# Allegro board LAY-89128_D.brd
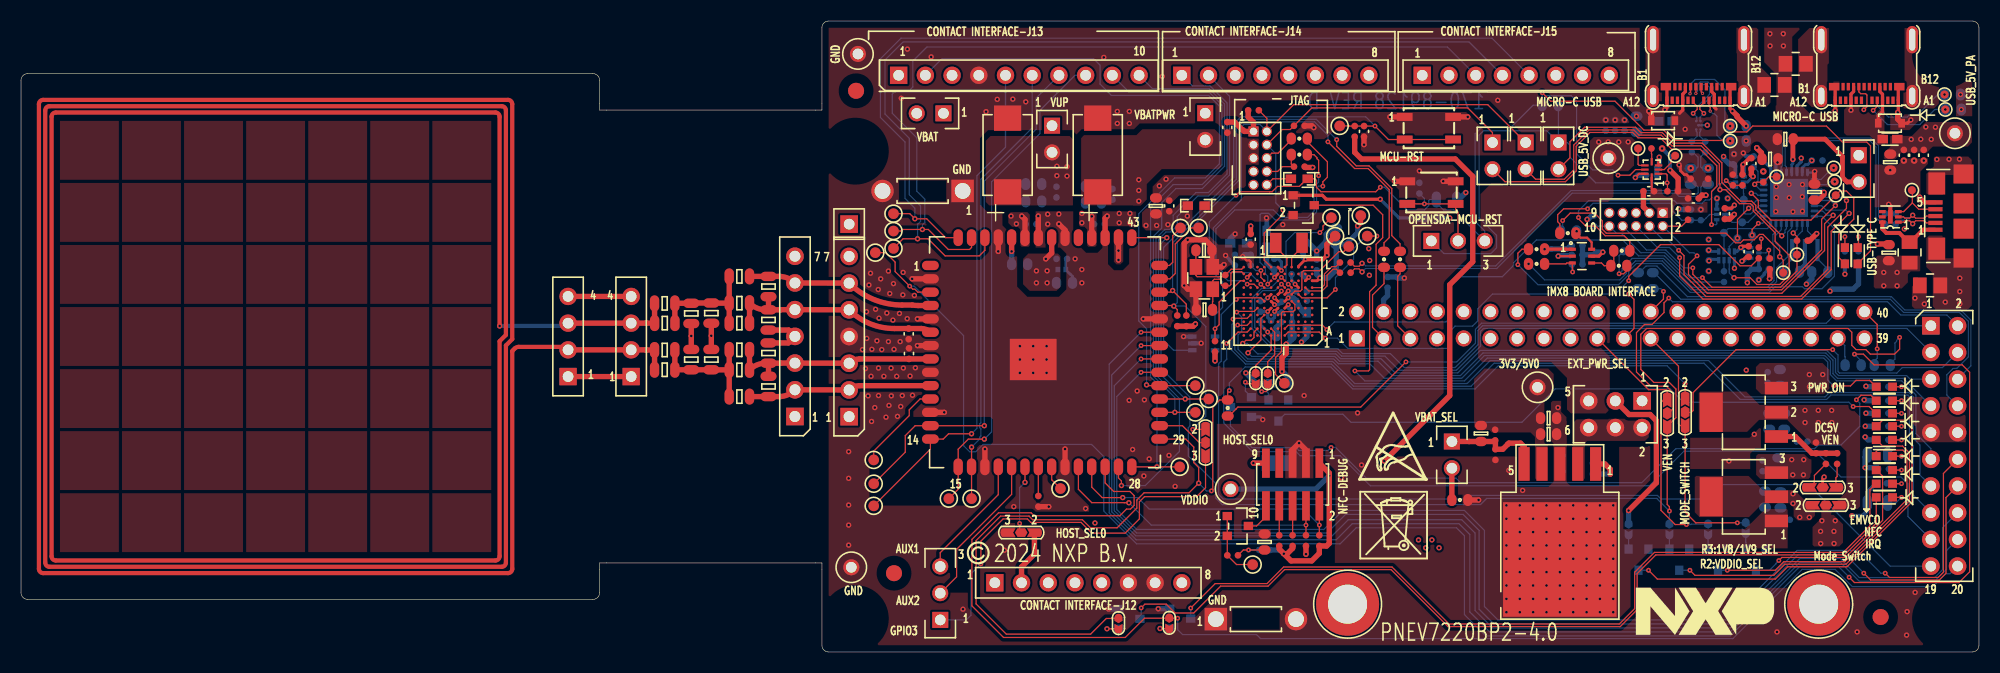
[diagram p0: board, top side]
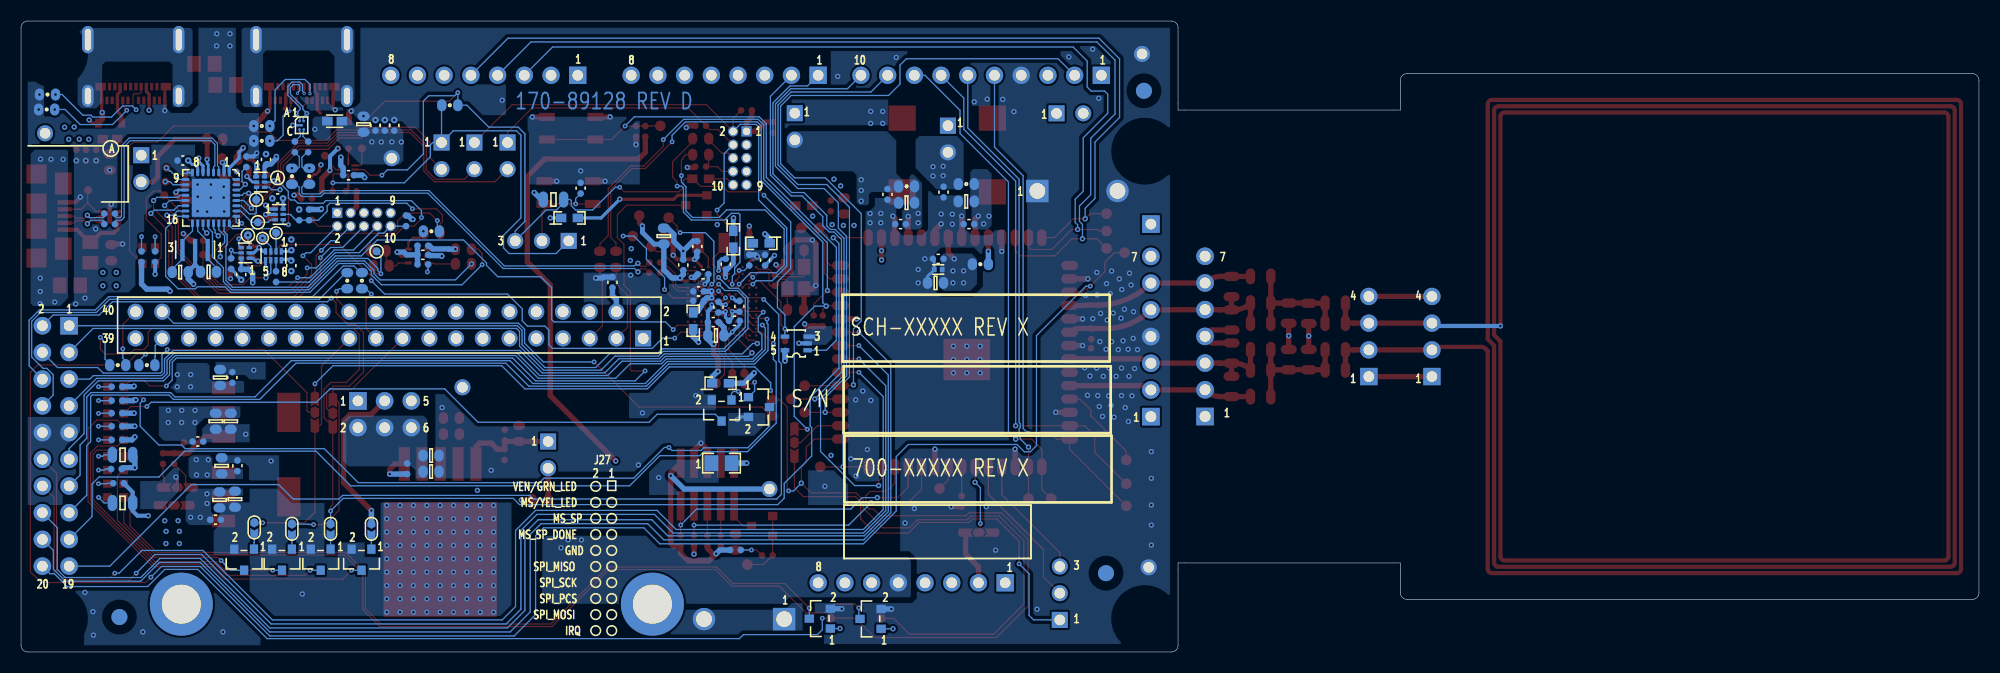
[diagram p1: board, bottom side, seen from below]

Outline 186.16 x 60 mm; copper layers: TOP, L2_GND_1, L3_INT_1, BOTTOM. Coordinates in mm from the lower left corner of the outline.
Outline path: 0,54.37 0,5.63 arc(0.19,5.19) 0.63,5 54.38,5 arc(54.83,5.19) 55.01,5.63 55.01,8.47 76.15,8.47 76.15,0.63 arc(76.33,0.19) 76.78,0 185.52,0 arc(185.97,0.19) 186.16,0.63 186.16,59.37 arc(185.97,59.81) 185.52,60 76.78,60 arc(76.33,59.81) 76.15,59.37 76.15,51.53 55.01,51.53 55.01,54.37 arc(54.83,54.81) 54.38,55 0.63,55 arc(0.19,54.81) 0,54.37

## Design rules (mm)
constraint set DEFAULT: min track width 0.114
net group SDA_USB_CONN_DN: nets SDA_USB_CONN_DN SDA_USB_DN
net group SDA_USB_CONN_DP: nets SDA_USB_CONN_DP SDA_USB_DP
net group USB_CC: nets USB_CC1_PA USB_CC2_PA
net group USB_CC_DC: nets USB_CC1_DC USB_CC2_DC
net group USB_DP1: nets USB_DN USB_DP
net group POWER: nets 3V3_K82_VOUT MCU_VBAT MCU_VDDA P5V0_SDA_USB_CONN_VBUS SH_3V3_VDDIO_E VDDPA VREF_OUT
net group USB0_DM: nets N28673663 N28673665 USB0_DM USB0_RDN
net group USB0_DP: nets N28673617 N28673619 USB0_DP USB0_RDP

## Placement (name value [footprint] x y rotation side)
C1  0.1uF  [CC0402_25]  165.58 17.7 90 bottom
C2  0.1uF  [CC0402_25]  166.07 26.1 90 bottom
C3  0.1uF  [CC0402_25]  102.53 40.69 0 bottom
C4  0.1uF  [CC0402_25]  96.03 40.69 0 bottom
C5  100UF  [CC7343]  93.8 47.26 90 top
C7  100UF  [CC7343]  102.37 47.26 90 top
C9  10uF  [CC0603_OV]  165.81 14.53 270 bottom
C10  0.1uF  [CC0402_25]  98.95 37.38 0 bottom
C11  0.1uF  [CC0402_25]  98.45 43.73 270 bottom
C14  10uF  [CC0603_OV]  147.17 18.68 180 bottom
C15  10uF  [CC0603_OV]  145.24 20.71 0 top
C16  10uF  [CC0603_OV]  107.91 42.42 90 top
C17  10uF  [CC0603_OV]  167.08 17.7 90 bottom
C19  0.1uF  [CC0402_25]  109.17 42.42 90 top
C20  680pF  [CC0603_OV]  138.81 20.78 270 top
C23  10uF  [CC0603_OV]  101.96 42.72 0 bottom
C24  4.7uF  [CC0603_OV]  177.72 46.58 270 top
C25  1.0UF  [0402_CC]  98.95 36.37 0 bottom
C26  0.1uF  [CC0402_25]  103.78 43.52 270 bottom
C28  10uF  [CC0603_OV]  167.64 21.94 270 bottom
C29  0.1uF  [CC0402_25]  167.66 12.57 180 bottom
C30  10uF  [CC0603_OV]  166.21 21.94 270 bottom
C31  10uF  [CC0603_OV]  96.29 42.85 0 bottom
C32  10uF  [CC0603_OV]  145.24 22.24 0 top
C33  10uF  [CC0603_OV]  167.23 26.1 90 bottom
C34  10uF  [CC0603_OV]  167.28 14.47 270 bottom
C35  10uF  [CC0603_OV]  99.21 35.1 0 bottom
C37  0.1uF  [CC0402_25]  169.34 20.02 180 bottom
C38  10uF  [CC0603_OV]  147.17 17.16 180 bottom
C41  0.1uF  [CC0402_25]  114.69 49.88 270 top
C44  1uF  [CC0603_OV]  125.04 39.55 90 bottom
C45  0.1uF  [CC0402_25]  123.19 36.8 90 bottom
C47  0.1uF  [CC0402_25]  121.31 35.92 180 bottom
C48  0.1uF  [CC0402_25]  121.87 38.56 90 bottom
C49  0.1uF  [CC0402_25]  120.34 31.37 180 bottom
C50  0.1uF  [CC0402_25]  121.74 33.4 0 bottom
C51  0.1uF  [CC0402_25]  121.74 34.29 0 bottom
C52  0.1uF  [CC0402_25]  119.15 36.88 90 bottom
C53  0.1uF  [CC0402_25]  115.42 37.26 270 bottom
C54  0.1uF  [CC0402_25]  119.85 32.79 90 bottom
C55  0.1uF  [CC0402_25]  117.86 32.87 90 bottom
C56  0.01uF  [CC0402_25]  118.34 31.49 180 bottom
C63  0.1uF  [CC0402_25]  179.01 47.24 270 top
C64  0.01uF  [CC0402_25]  179.99 47.24 270 top
C65  1000pF  [CC0402_25]  180.91 47.24 270 top
C66  4.7uF  [CC0603_OV]  153.59 50.19 90 bottom
C67  0.1uF  [CC0402_25]  152.46 50.08 90 bottom
C68  0.01uF  [CC0402_25]  151.57 50.08 90 bottom
C69  1000pF  [CC0402_25]  150.67 50.08 90 bottom
C78  10uF  [CC0603_OV]  120.09 30.1 180 bottom
C79  0.1uF  [CC0402_25]  154.76 43.81 180 top
C80  0.1uF  [CC0402_25]  147.95 37.77 180 bottom
C81  0.1uF  [CC0402_25]  155.02 45.34 0 bottom
C82  10uF  [CC0603_OV]  170.52 43.74 90 top
C83  1uF  [CC0603_OV]  166.29 46.87 0 top
C84  0.1uF  [CC0402_25]  170.77 46.74 0 bottom
C85  1000pF  [CC0402_25]  132.95 44.11 90 bottom
C86  10uF  [CC0603_OV]  177.58 37.97 90 top
C87  22 PF  [CC0603_OV]  168.33 36.15 0 bottom
C88  22 PF  [CC0603_OV]  171.02 36.12 180 bottom
C89  2.2uF  [CC0603_OV]  167.74 48.77 180 top
C91  10uF  [CC0603_OV]  118.23 10.46 90 top
C92  68pF  [CC0805_OV]  71.07 28.43 90 top
C93  68pF  [CC0805_OV]  71.07 31.57 90 top
C94  0.1uF  [CC0402_25]  164.51 46.46 270 top
C95  68pF  [CC0805_OV]  65.63 32.22 90 top
C96  68pF  [CC0805_OV]  63.73 27.8 90 top
C97  18pF  [CC0805_OV]  68.3 33.17 180 top
C98  100pF  [CC0805_OV]  63.73 32.2 90 top
C100  100pF  [CC0805_OV]  65.63 27.8 90 top
C101  47pF  [CC0805_OV]  68.3 28.73 180 top
C102  180pF  [CC0402_25]  84.4 30.25 270 top
C103  18pF  [CC0805_OV]  68.3 26.82 180 top
C104  180pF  [CC0402_25]  84.42 28.37 90 top
C105  47pF  [CC0805_OV]  68.3 31.27 180 top
C134  0.1uF  [CC0402_25]  129.92 35.15 90 bottom
C151  0.1uF  [CC0402_25]  116.92 39.25 90 top
C152  22 PF  [CC0603_OV]  112.47 38.2 180 top
C153  22 PF  [CC0603_OV]  112.52 32.54 0 top
C154  1000pF  [CC0402_25]  127.69 49.51 270 top
C155  0.1uF  [CC0402_25]  164.26 38.07 90 top
C156  0.1uF  [CC0402_25]  165.22 35.89 270 bottom
C157  0.1uF  [CC0402_25]  160.46 38.71 90 bottom
C158  0.1uF  [CC0402_25]  160.46 36.73 270 bottom
C159  0.1uF  [CC0402_25]  162.86 46.84 90 bottom
C160  0.1uF  [CC0402_25]  161.99 41.68 270 top
C161  0.1uF  [CC0402_25]  161.75 43.13 0 bottom
C162  0.1uF  [CC0402_25]  159 43.13 0 top
D1  RED  [LED_0603]  177.16 25.22 180 top
D2  RED  [LED_0603]  177.16 22.69 180 top
D3  LED GREEN  [LED_0603]  177.16 23.9 180 top
D4  PESD5V0U1UA,115  [SOD-323-A]  177.69 50.28 0 top
D5  PESD5V0U1UA,115  [SOD-323-A]  156.12 50.53 180 top
D8  RED  [LED_0603]  174.62 37.68 270 top
D9  LED GREEN  [LED_0603]  173.41 37.68 270 top
D11  LED GREEN  [LED_0603]  177.16 14.71 180 top
D12  BAS70-05  [SOT23_A]  115.69 11.98 270 top
D15  ORANGE  [LED_0603]  177.16 16 180 top
D16  LED_YELLOW  [LED_0603]  177.16 17.3 180 top
D17  GREEN  [LED_0603]  177.16 18.62 180 top
D18  BLUE  [LED_0603]  177.16 20.17 180 top
D19  ORANGE  [LED_0603]  177.16 21.46 180 top
J1  HDR 1X2 TH  [HDR_1X2]  98.03 50.05 0 top
J2  HDR 1X2 TH  [HDR_1X2]  112.59 51.24 0 top
J3  HDR 1X2 TH  [HDR_1X2]  136.04 20.02 0 top
J4  HDR 1X2 TH  [HDR_1X2]  87.7 51.22 270 top
J5  HDR_2X3  [HDR203]  154.13 23.88 270 top
J6  105450-0101  [CON24_USB_TYPEC_RA_SMT]  175.49 56.23 180 top
J7  105450-0101  [CON24_USB_TYPEC_RA_SMT]  159.49 56.23 180 top
J8  LB 03 G  [JUMP2_7P62_TH]  113.6 3.12 0 top
J9  LB 03 G  [JUMP2_7P62_TH]  89.53 43.84 180 top
J10  HDR TH 1X3  [HDR103]  87.4 3.05 180 top
J12  SKT_1X8  [CON_SKT1X8_TH]  92.59 6.58 90 top
J13  SKT_1X10  [CON_SKT1X10_TH_104L]  83.44 54.84 90 top
J14  SKT_1X8  [CON_SKT1X8_TH]  110.37 54.84 90 top
J15  SKT_1X8  [CON_SKT1X8_TH]  133.23 54.84 90 top
J27  TSW-110-07-F-D  [HDR210]  181.58 31.02 0 top
J28  FTSH-105-01-L-DV-K  [HDR205_10M_50_SM_K]  120.9 15.93 180 top
J29  CON_1X4  [CON_SKT1X4_TH]  52.01 26.19 180 top
J30  CON_1X4  [CON_SKT1X4_TH]  58.01 26.19 180 top
J31  SKT_1x7  [CON_1X7_SKT_2P54_TH]  78.73 22.38 90 top
J32  SKT_1x7  [CON_1X7_SKT_2P54_TH]  73.58 22.39 90 top
J33  -  [HDR_1X1]  78.73 40.69 0 top
J35  HDR 2X5  [HDR_5X2_FTSH_TH_NSP]  117.18 49.5 0 top
J43  CON_2X20  [CON_SKT2X20_TH]  127.01 29.82 270 bottom
J56  HDR TH 1X3  [HDR103]  134.09 39.09 90 top
J57  ZX62-AB-5P  [MICRO_USB_CONN_9PIN]  184.69 41.45 90 top
J58  HDR 1X2 TH  [SH_HDR102_BOTTOM]  146.18 48.45 0 top
J59  HDR 1X2 TH  [HDR_1X2]  143.05 48.45 0 top
J60  HDR 1X2 TH  [HDR_1X2]  139.9 48.45 0 top
J61  HDR 1X2 TH  [SH_HDR102_BOTTOM]  174.73 47.24 0 top
J62  HDR 2X5  [HDR_5X2_FTSH_TH_NSP]  156.09 41.76 270 top
L4  330 OHM  [IND_0805]  179.56 38 270 top
L5  330 OHM  [IND_0805]  181.51 34.86 180 top
L6  120 OHM@100MHZ  [IND_0603]  177.7 48.77 180 top
L7  330 OHM  [IND_0805]  168.73 55.93 180 top
L8  120 OHM@100MHZ  [IND_0603]  156.34 50.48 0 bottom
L9  330 OHM  [IND_0805]  166.71 53.92 0 top
NOREF  -  []  159.89 49.48 90 top
NOREF#2  -  []  92.76 21.38 90 top
NOREF#3  -  []  173.2 44.08 90 top
NOREF#4  -  []  158.99 52.46 0 top
NOREF#5  -  []  93.84 11.35 0 top
NOREF#6  -  []  112.62 18.66 90 top
NOREF#7  -  []  172.49 52.46 0 top
NOREF#8  -  []  155.17 52.87 90 top
NOREF#9  -  []  76.15 45.75 0 top
NOREF#10  -  [unnamed#2]  176.8 3.32 0 top
NOREF#11  -  []  152.84 11.18 90 top
NOREF#12  -  []  171.17 52.87 90 top
NOREF#13  -  []  92.47 42.84 90 top
NOREF#14  -  []  170.04 15.65 0 top
NOREF#15  -  []  155.17 52.87 0 top
NOREF#16  -  [unnamed#2]  79.32 3.17 0 top
NOREF#17  -  []  147.74 36.54 0 top
NOREF#18  -  []  73.58 22.39 90 top
NOREF#19  -  []  75.85 43.84 0 top
NOREF#20  -  []  76.15 59.37 0 top
NOREF#21  -  []  107.85 8.94 0 top
NOREF#22  -  [unnamed#2]  83 7.49 0 top
NOREF#23  -  []  155.17 52.87 90 top
NOREF#24  -  []  104.34 2.21 90 top
NOREF#25  -  []  -284.54 213.41 0 top
NOREF#26  -  []  79.37 23.9 0 top
NOREF#27  -  []  89.1 17.6 0 top
NOREF#28  -  []  156.49 52.46 0 top
NOREF#29  -  []  172.39 53.76 0 top
NOREF#30  -  []  149.09 36.54 90 top
NOREF#31  -  []  159.28 49.69 0 top
NOREF#32  -  []  113.6 3.12 0 top
NOREF#33  -  []  112.62 19.91 90 top
NOREF#34  -  []  55.01 45.21 0 top
NOREF#35  -  []  158.22 21.54 90 top
NOREF#36  -  []  170.35 13.96 0 top
NOREF#37  -  []  171.17 52.87 90 top
NOREF#38  -  []  95.1 11.35 0 top
NOREF#39  -  []  119.66 2.12 90 top
NOREF#40  -  [unnamed#2]  79.32 47.63 0 top
NOREF#41  -  []  129.06 5.39 0 top
NOREF#42  -  []  79.32 47.63 0 top
NOREF#43  -  []  155.17 52.87 90 top
NOREF#44  -  [unnamed#2]  182.97 3.17 0 top
NOREF#45  -  []  127.33 8.89 0 top
NOREF#46  -  []  147.49 36.99 0 top
NOREF#47  -  []  170.35 13.96 0 top
NOREF#48  -  []  156.72 11.18 90 top
NOREF#49  -  []  185.99 0.21 0 top
NOREF#50  -  []  171.17 52.87 90 top
NOREF#51  -  []  149.33 36.99 90 top
NOREF#52  -  []  153.54 1.63 0 top
NOREF#53  -  []  91.01 9.4 0 top
NOREF#54  -  []  180.06 44.08 0 top
NOREF#55  -  []  81.91 43.84 0 top
NOREF#56  -  []  97.91 21.36 90 top
NOREF#57  -  []  156.51 22.7 90 top
NOREF#58  -  [unnamed#3]  170.92 4.55 0 top
NOREF#59  -  []  159.68 49.69 90 top
NOREF#60  -  []  156.39 53.76 0 top
NOREF#61  -  [unnamed#2]  182.97 56.83 0 top
NOREF#62  -  []  164.06 44.08 0 top
NOREF#63  -  []  109.17 2.23 90 top
NOREF#64  -  []  115.16 2.12 0 top
NOREF#65  -  []  -309.18 -308.18 0 top
NOREF#66  -  []  74.22 23.92 0 top
NOREF#67  -  []  189.2 44.08 90 top
NOREF#68  -  []  159.07 49.48 0 top
NOREF#69  -  []  77.91 1.9 0 top
NOREF#70  -  []  158.22 22.79 90 top
NOREF#71  -  []  182.45 26.16 0 top
NOREF#72  -  []  171.17 52.87 0 top
NOREF#73  -  []  160.4 11.18 90 top
NOREF#74  -  []  175.24 53.76 0 top
NOREF#75  -  [unnamed#3]  126.13 4.55 0 top
NOREF#76  -  []  108.25 20.25 90 top
NOREF#77  -  []  156.51 21.45 90 top
NOREF#78  -  []  75.63 -84.03 0 top
NOREF#79  -  []  86.56 17.71 0 top
NOREF#80  -  []  78.73 22.38 90 top
NOREF#81  -  []  108.15 17.71 90 top
NOREF#82  -  [unnamed#2]  79.39 53.37 0 top
NOREF#83  -  []  159.24 53.76 0 top
NOREF#84  -  []  108.25 20.25 90 top
NOREF#85  -  []  170.04 15.65 0 top
NOREF#86  -  []  174.99 52.46 0 top
NOREF#87  -  []  55.01 12.35 0 top
NOREF#88  -  []  163.98 11.3 90 top
NOREF#89  -  []  107.95 20.81 180 bottom
NOREF#90  -  []  90.07 14.02 0 bottom
NOREF#91  -  []  107.87 14.23 180 bottom
NOREF#92  -  [unnamed#2]  176.8 3.32 180 bottom
NOREF#93  -  [unnamed#2]  79.39 53.37 180 bottom
NOREF#94  -  [unnamed#2]  83 7.49 180 bottom
NOREF#95  -  []  108.05 27.62 180 bottom
P1  PN76xx MODULE BASE  [MODULE56_1P52_23X23MM]  97.36 28.5 0 top
Q1  NX3008NBK  [SOT23_A]  121.95 42.49 270 top
Q2  NX3008NBK  [SOT23_A]  157.66 8.78 0 bottom
Q3  NX3008NBK  [SOT23_A]  153.78 8.78 0 bottom
Q4  NX3008NBK  [SOT23_A]  164.95 8.78 0 bottom
Q5  NX3008NBK  [SOT23_A]  161.34 8.78 0 bottom
Q6  NX3008NBK  [SOT23_A]  105.38 3.15 90 bottom
Q7  NX3008NBK  [SOT23_A]  110.21 3.17 90 bottom
Q8  NX3008NBK  [SOT23_A]  119.55 22.96 0 bottom
Q9  NX3008NBK  [SOT23_A]  115.99 23.29 270 bottom
R1  180  [RC0402_25]  170.66 19.41 270 top
R2  3 PIN 0603 SHORT 1-2  [3PIN_0603_SOLDER_BLOB_JUMPER_SHORT]  171.6 13.96 180 top
R3  3 PIN 0603 SHORT 1-2  [3PIN_0603_SOLDER_BLOB_JUMPER_SHORT]  171.3 15.65 180 top
R4  80.6  [RC0402_25]  171.6 18.39 270 top
R5  2.74K  [RC0402_25]  140.18 18.77 270 top
R6  3.9K  [RC0603_OV]  136.8 14.45 0 top
R7  3 PIN 0603 SHORT 1-2  [3PIN_0603_SOLDER_BLOB_JUMPER_SHORT]  95.1 11.35 0 top
R8  3 PIN 0603 SHORT 1-2  [3PIN_0603_SOLDER_BLOB_JUMPER_SHORT]  112.62 19.91 90 top
R9  33  [RC0402_25]  125.91 37.04 180 top
R10  5.1K  [RC0603_OV]  163.26 50.02 0 bottom
R11  5.1K  [RC0603_OV]  163.26 48.61 0 bottom
R12  27  [RC0402_25]  160.13 48.03 270 bottom
R13  10K  [RC0402_25]  160.4 45.5 270 top
R14  95.3  [RC0402_25]  172.67 18.39 270 top
R15  3 PIN 0603 JUMPER  [3PIN_0603_SOLDER_BLOB_JUMPER]  156.51 22.7 90 top
R16  3 PIN 0603 SHORT 1-2  [3PIN_0603_SOLDER_BLOB_JUMPER_SHORT]  158.22 22.79 90 top
R17  0  [RC0603_OV]  101.96 44.28 180 bottom
R18  10K  [RC0402_25]  158.75 45.5 270 top
R19  27  [RC0402_25]  158.86 48.03 270 bottom
R20  1.8K  [RC0402_25]  177.04 25.22 0 bottom
R21  10K  [RC0402_25]  149.44 17.43 270 bottom
R23  0  [RC0603_OV]  96.29 44.5 180 bottom
R25  0  [RC0603_OV]  158.75 45.24 90 bottom
R26  0  [RC0603_OV]  94.94 36.88 180 bottom
R27  0  [RC0603_OV]  160.4 45.24 90 bottom
R28  4.7K  [RC0402_25]  140.16 20.62 270 top
R36  10K  [RC0402_25]  117.18 51.51 0 top
R37  10K  [RC0402_25]  121.54 50.04 0 top
R38  10K  [RC0402_25]  121.54 46.15 180 top
R39  0  [RC0603_OV]  121.54 48.82 0 top
R47  0  [RC0603_OV]  121.54 47.29 0 top
R56  10K  [RC0402_25]  120.9 10.59 270 top
R60  1K  [RC0402_25]  115.2 9.19 180 top
R62  1.5K  [RC0805_OV]  176.5 14.17 0 bottom
R64  10K  [RC0402_25]  122.17 10.59 270 top
R67  10K  [RC0402_25]  123.44 10.59 270 top
R68  1K  [RC0402_25]  118.23 9.7 180 bottom
R69  2.2K  [RC0402_25]  176.88 16.04 0 bottom
R71  10K  [RC0402_25]  119.63 10.59 270 top
R73  2.2 OHM  [RC0805_OV]  61.2 28.72 180 top
R74  2.2 OHM  [RC0805_OV]  61.2 33.15 180 top
R75  0  [RC0805_OV]  68.3 35.71 180 top
R76  1.5K  [RC0805_OV]  71.07 34.75 90 top
R77  1.5K  [RC0805_OV]  71.07 25.25 90 top
R78  10K  [RC0402_25]  166.17 36.93 270 bottom
R79  2.2 OHM  [RC0805_OV]  61.21 31.27 180 top
R80  2.2 OHM  [RC0805_OV]  61.2 26.84 180 top
R81  0  [RC0805_OV]  68.3 24.28 180 top
R82  1.0K  [RC0402_25]  161.91 35.69 270 bottom
R83  10K  [RC0402_25]  149.55 41 90 bottom
R84  0  [RC0603_OV]  152.2 38.15 0 top
R85  5.1K  [RC0603_OV]  183.64 53.01 0 bottom
R86  5.1K  [RC0603_OV]  183.72 51.59 0 bottom
R89  10K  [RC0402_25]  96.72 14.33 90 top
R90  2.2K  [RC0402_25]  110.79 31.49 90 top
R91  2.2K  [RC0402_25]  109.93 31.49 90 top
R122  0  [RC0603_OV]  155.14 35.31 270 bottom
R127  0  [RC0603_OV]  131.11 37.34 90 top
R137  0  [RC0603_OV]  129.59 37.34 90 top
R141  0  [RC0603_OV]  114.73 23.2 270 top
R142  0  [RC0603_OV]  176.96 27.28 180 bottom
R144  0  [RC0603_OV]  153.75 35.31 90 bottom
R152  0  [RC0603_OV]  174.19 27.28 0 bottom
R164  1.8K  [RC0402_25]  177.09 17.4 0 bottom
R165  1.5K  [RC0805_OV]  176.5 18.75 0 bottom
R172  1.8K  [RC0402_25]  177.04 20.17 0 bottom
R173  2.2K  [RC0402_25]  177.04 21.46 0 bottom
R177  180  [RC0402_25]  177.04 22.71 0 bottom
R178  220  [RC0402_25]  177.04 23.9 0 bottom
R180  10K  [RC0402_25]  116.92 37.26 270 bottom
R181  1M  [RC0402_25]  114.5 35.33 90 top
R182  33  [RC0402_25]  125.91 36.07 180 top
R183  10K  [RC0402_25]  113.52 29.05 90 top
R184  4.7K  [RC0402_25]  126.8 49.51 90 top
R185  180K  [RC0805_OV]  135.53 43.03 180 bottom
R186  10K  [RC0402_25]  157.05 43.81 180 top
R187  10K  [RC0402_25]  147.95 38.63 180 bottom
R188  4.7K  [RC0402_25]  155.52 47.88 0 top
R189  0  [RC0603_OV]  144.09 38.3 180 top
R190  10K  [RC0402_25]  147.95 36.86 0 bottom
R191  100  [RC0402_25]  174.7 37.59 90 bottom
R192  0  [RC0603_OV]  144.09 36.91 180 top
R193  33  [RC0402_25]  177.74 40.68 180 bottom
R194  33  [RC0402_25]  177.74 41.68 180 bottom
R195  0  [RC0603_OV]  145.39 51.99 180 bottom
R196  1.0K  [RC0402_25]  165.22 37.95 270 top
R197  4.7K  [RC0402_25]  166.27 36.91 90 top
R198  4.7K  [RC0402_25]  169.36 39.12 180 top
R199  220  [RC0402_25]  173.41 37.59 90 bottom
R200  4.7K  [RC0402_25]  165.65 45.19 270 top
R201  10K  [RC0402_25]  162.75 44.89 90 top
R202  4.7K  [RC0402_25]  163.67 44.89 270 top
R203  10K  [RC0402_25]  164.74 46.62 90 bottom
R204  0  [RC0603_OV]  147.06 39.83 180 top
R205  10K  [RC0402_25]  158.77 41.57 90 bottom
R206  4.7K  [RC0402_25]  159.71 41.57 270 bottom
R207  10K  [RC0402_25]  158.49 41.61 270 top
R208  0  [RC0603_OV]  147.14 40 180 bottom
R209  0  [RC0603_OV]  151.92 36.73 0 top
SH1  0  [SH0603]  111.73 42.44 180 top
SH2  0  [SH0603]  121.54 45 180 top
SH3  0  [SH0603]  119.65 25.55 180 bottom
SH4  0  [SH0603]  122.25 31.49 90 bottom
SH5  0  [SH0603]  115.77 38.86 0 bottom
SH6  0  [SH0603]  118.44 39.25 270 bottom
SH7  0  [SH0603]  134.01 41.27 180 bottom
SJ3  0402 JUMPER  [0402_SOLDER_BLOB_JUMPER_SHORT]  104.34 2.74 270 top
SJ4  0402 JUMPER  [0402_SOLDER_BLOB_JUMPER_SHORT]  109.17 2.76 270 top
SJ7  0402 JUMPER  [0402_SOLDER_BLOB_JUMPER_SHORT]  163.98 11.84 270 bottom
SJ8  0402 JUMPER  [0402_SOLDER_BLOB_JUMPER_SHORT]  160.4 11.71 270 bottom
SJ9  0402 JUMPER  [0402_SOLDER_BLOB_JUMPER_SHORT]  156.72 11.71 270 bottom
SJ10  0402 JUMPER  [0402_SOLDER_BLOB_JUMPER_SHORT]  152.84 11.71 270 bottom
SJ11  JUMPER_2  [JUMP1X2_0805]  119.56 17.96 180 bottom
SJ12  0402 JUMPER  [0402_SOLDER_BLOB_JUMPER_SHORT]  118.53 26.03 270 top
SJ13  0402 JUMPER  [0402_SOLDER_BLOB_JUMPER_SHORT]  117.39 26.03 270 top
SW1  SKRPABE010  [SW4_SKRP]  133.86 49.81 0 top
SW12  SKRPABE010  [SW4_SKRP]  134.1 43.69 0 top
TP1  TEST POINT BLACK  [TEST_LOOP]  79.57 56.87 0 top
TP2  TEST POINT RED  [TEST_LOOP]  183.87 49.33 0 top
TP3  TEST POINT RED  [TEST_LOOP]  150.92 46.96 180 top
TP5  TEST POINT BLACK  [TEST_LOOP]  78.94 8.05 0 top
TP6  TEST POINT RED  [TEST_LOOP]  115 15.49 90 top
TP7  TEST POINT RED  [TEST_LOOP]  144.19 25.17 180 top
TP8  -  [TPAD_030]  182.96 51.59 0 top
TP9  -  [TPAD_030]  182.88 53.01 0 top
TP10  -  [TPAD_030]  162.5 48.61 270 top
TP11  -  [TPAD_030]  162.5 50.02 270 top
TP15  -  [TPAD_040]  81.22 37.97 0 top
TP16  -  [TPAD_040]  112.92 24.06 0 top
TP17  -  [TPAD_040]  111.65 25.33 0 top
TP18  -  [TPAD_040]  111.65 22.78 0 top
TP19  -  [TPAD_040]  110.16 17.6 0 top
TP20  -  [TPAD_040]  111.96 40.33 0 top
TP24  -  [TPAD_040]  117.1 8.31 180 top
TP25  -  [TPAD_040]  90.37 14.58 0 top
TP26  -  [TPAD_040]  81.07 16 0 top
TP27  -  [TPAD_040]  81.07 13.89 0 top
TP28  -  [TPAD_040]  88.21 14.58 0 top
TP32  -  [TPAD_040]  110.23 40.33 0 top
TP33  -  [TPAD_040]  98.83 15.54 0 top
TP39  -  [TPAD_040]  82.95 40.03 0 top
TP43  -  [TPAD_040]  82.95 38.38 0 top
TP50  -  [TPAD_040]  82.95 41.68 0 top
TP52  -  [TPAD_040]  81.07 18.26 0 top
TP56  -  [TPAD_040]  127.38 41.5 90 top
TP57  -  [TPAD_040]  124.94 39.55 180 top
TP58  -  [TPAD_040]  120.11 25.55 90 top
TP59  -  [TPAD_040]  128 39.55 90 top
TP60  -  [TPAD_040]  126.24 38.56 90 top
TP61  -  [TPAD_040]  124.59 41.3 90 top
TP62  -  [TPAD_040]  125.37 50.03 0 top
TP63  -  [TPAD_030]  157.27 47.19 90 top
TP64  -  [TPAD_030]  153.75 47.88 90 top
TP65  -  [TPAD_030]  179.78 43.92 270 top
TP66  -  [TPAD_030]  172.44 44.73 0 top
TP67  -  [TPAD_030]  172.34 46.04 0 top
TP68  -  [TPAD_030]  164.59 39.63 0 bottom
TP69  -  [TPAD_030]  167.54 36.07 0 top
TP70  -  [TPAD_030]  152.35 38.1 180 bottom
TP71  -  [TPAD_030]  161.91 39.86 270 bottom
TP72  -  [TPAD_030]  168.85 37.78 0 top
TP73  -  [TPAD_030]  163.2 39.35 270 bottom
TP74  -  [TPAD_030]  172.54 43.43 0 top
TP75  -  [TPAD_030]  163.79 43.01 180 bottom
TP76  -  [TPAD_030]  166.92 45.19 0 top
TP77  -  [TPAD_030]  163.64 40.86 270 bottom
U2  PESD1USB30  [WLCSP5_0P4_0P82X1P22]  159.48 50.09 180 bottom
U5  LP3856ES-ADJ  [REG5_TO263]  146.31 10.84 180 top
U6  NCP1117ST33T3G  [SOT223]  163.8 14.76 90 top
U7  NCP1117STAT3G  [SOT223]  163.8 22.79 90 top
U17  RClamp0854P.TCT  [SLP1616P6]  177.73 41.38 90 top
U19  74LVC2T45GT,115  [XSON_8P]  162.16 37.67 0 bottom
U20  74LVCH1T45  [UDFN6_1X1P5MM]  163.39 44.69 180 bottom
U22  MK82FN256VDC15  [BGA121_0P65_8X8MM]  119.51 33.35 180 top
U23  74LVC1G125GW-Q100  [SC70-5]  112.44 29.34 90 bottom
U25  NTSX2102GU8H  [XQFN8_1P45X1P25MM]  155.04 45.87 90 top
U26  MK20DX128VFM5  [QFN32_S142EP]  168.1 43.18 270 bottom
U27  NL27WZ14DFT2G  [SC-88_6P]  148.41 37.64 0 top
U28  74LVCH1T45  [UDFN6_1X1P5MM]  164.84 37.95 0 bottom
U29  74LVCH1T45  [UDFN6_1X1P5MM]  161.61 41.61 180 bottom
X1  8 MHz  [XTAL3_3P35X1P45_SM]  169.61 38.22 180 bottom
Y1  32.768KHZ  [XTAL2-3P2X1P5-SM]  120.55 38.9 0 top
Y2  12MHZ  [XTAL4_3P3X2P6_SM_FL]  112.51 35.56 90 top

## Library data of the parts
C1-C4 C10 C11 C19 C20 C23-C26 C29 C31 C37 C49 C63-C69 C82 C83 C85-C89 C91-C93 C95-C98 C100-C105 C152-C154 = CAP_NP
C5 C7 = CAP_POL
C9 C14-C17 C28 C30 C32-C35 C38 C41 C44 C45 C47 C48 C50-C55 C78-C81 C84 C94 C134 C151 C155-C162 = CAP_NP: tolerance: 10%
C56 = CAP_NP: tolerance: 20%
D1-D3 D8 D9 D11 D15-D19 = LED
D4 D5 = DIODE_SCHTKY
D12 = DIODE_DUAL SCH_3P
J1-J4 J58-J61 = CONN_HDR_2X1
J5 = CONN_HDR_3X2
J6 J7 = USB24_TYPEC_105450
J8 J9 = JUMPER1X2_TH
J10 J56 = CONN_HDR_3X1
J12 J14 J15 = CONN_HDR_8X1
J13 = CONN_HDR_10X1
J27 = CONN_HDR_10X2
J28 J35 J62 = CONN_HDR_5X2
J29 J30 = CONN_HDR_4X1
J31 J32 = CONN_HDR_7X1
J33 = CONN_HDR_1X1_TH
J43 = CONN_RCPT_2X20
J57 = MICRO_USB_CONN_9PIN
L4 L5 = BEAD
L6 L8 = BLM18R
L7 L9 = BEAD: tolerance: 25%
P1 = TP_RECT_56P_EP
Q1-Q9 = NMOS_NX3008NBK
R1 R4-R6 R10 R11 R14 R17 R20 R21 R23 R26 R28 R56 R60 R62 R64 R67-R69 R71 R73-R77 R79-R81 R83-R86 R90 R91 R164 R165 R172 R173 R177 R178 R181 R189 R192 R199 R203 R204 R207-R209 = RES
R2 R3 R7 R8 R16 = 3_Pad_Solder_Blob_Jumper_short
R9 R182 = RES: tolerance: 1%; signal model: RES_RC0402_25_DISCRETE_0.4MM_470-75790_33_1%_33
R12 R19 = RES: signal model: RES_RC0402_25_DISCRETE_0.45_MM_470-75611_27_27
R13 R18 R78 R89 R183 R184 R186 R187 R190 R195 R201 R205 = RES: tolerance: 5%
R15 = 3_Pad_Solder_Blob_Jumper
R25 R27 = RES: tolerance: 1%; signal model: RES_RC0603_OV_DISCRETE_0.6MM_470-80866_0_1%_0
R36-R39 R47 R82 R122 R127 R137 R141 R142 R144 R152 R180 R185 R188 R191 R196-R198 R200 R202 R206 = RES: tolerance: 1%
R193 R194 = RES: signal model: RES_RC0402_25_DISCRETE_0.4MM_470-75790_33_33
SH1-SH7 = RES_SHORT-2
SJ3 SJ4 SJ7-SJ10 SJ12 SJ13 = 2_Pad_Solder_Blob_Jumper
SJ11 = 2-PIN_PAD
SW1 SW12 = SW_TC_SPST_4P
TP1-TP3 TP5-TP11 TP15-TP20 TP24-TP28 TP32 TP33 TP39 TP43 TP50 TP52 TP56-TP77 = TESTLOOP
U2 = PESD1USB30
U5 = LT1963A_DDPAK_6P
U6 = LD1117AS18
U7 = NCP1117
U17 = RCLAMP1654P_NEW
U19 = 74LVC2T45DC_8P
U20 U28 U29 = 74LVCH1T45_6P
U22 = MK82FN256VDC_BGA_121P_A
U23 = 1G125
U25 = NTSX2102GD
U26 = PK20DX128V_QFN_32P
U27 = NL27WZ14
X1 = XTAL_CS
Y1 = XTAL
Y2 = XTAL_13

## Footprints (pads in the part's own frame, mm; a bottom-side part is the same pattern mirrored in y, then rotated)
3PIN_0603_SOLDER_BLOB_JUMPER
  custom 0.203x0.203 smd: 1(0,0) 2(1.254,0) 3(-1.254,0)
3PIN_0603_SOLDER_BLOB_JUMPER_SHORT
  custom 0.203x0.203 smd: 1(0,0) 2(1.254,0) 3(-1.254,0)
0402_CC
  rect 0.457x0.508 smd: 1(-0.375,0) 2(0.375,0)
0402_SOLDER_BLOB_JUMPER_SHORT
  custom 0.191x0.191 smd: 1(-0.445,0) 2(0.533,0)
BGA121_0P65_8X8MM
  round 0.254 smd: A1(-3.25,3.25) A2(-2.6,3.25) A3(-1.95,3.25) A4(-1.3,3.25) A5(-0.65,3.25) A6(0,3.25) A7(0.65,3.25) A8(1.3,3.25) A9(1.95,3.25) A10(2.6,3.25) A11(3.25,3.25) B1(-3.25,2.6) B2(-2.6,2.6) B3(-1.95,2.6) B4(-1.3,2.6) B5(-0.65,2.6) B6(0,2.6) B7(0.65,2.6) B8(1.3,2.6) B9(1.95,2.6) B10(2.6,2.6) B11(3.25,2.6) C1(-3.25,1.95) C2(-2.6,1.95) C3(-1.95,1.95) C4(-1.3,1.95) C5(-0.65,1.95) C6(0,1.95) C7(0.65,1.95) C8(1.3,1.95) C9(1.95,1.95) C10(2.6,1.95) C11(3.25,1.95) D1(-3.25,1.3) D2(-2.6,1.3) D3(-1.95,1.3) D4(-1.3,1.3) D5(-0.65,1.3) D6(0,1.3) D7(0.65,1.3) D8(1.3,1.3) D9(1.95,1.3) D10(2.6,1.3) D11(3.25,1.3) E1(-3.25,0.65) E2(-2.6,0.65) E3(-1.95,0.65) E4(-1.3,0.65) E5(-0.65,0.65) E6(0,0.65) E7(0.65,0.65) E8(1.3,0.65) E9(1.95,0.65) E10(2.6,0.65) E11(3.25,0.65) F1(-3.25,0) F2(-2.6,0) F3(-1.95,0) F4(-1.3,0) F5(-0.65,0) F6(0,0) F7(0.65,0) F8(1.3,0) F9(1.95,0) F10(2.6,0) F11(3.25,0) G1(-3.25,-0.65) G2(-2.6,-0.65) G3(-1.95,-0.65) G4(-1.3,-0.65) G5(-0.65,-0.65) G6(0,-0.65) G7(0.65,-0.65) G8(1.3,-0.65) G9(1.95,-0.65) G10(2.6,-0.65) G11(3.25,-0.65) H1(-3.25,-1.3) H2(-2.6,-1.3) H3(-1.95,-1.3) H4(-1.3,-1.3) H5(-0.65,-1.3) H6(0,-1.3) H7(0.65,-1.3) H8(1.3,-1.3) H9(1.95,-1.3) H10(2.6,-1.3) H11(3.25,-1.3) J1(-3.25,-1.95) J2(-2.6,-1.95) J3(-1.95,-1.95) J4(-1.3,-1.95) J5(-0.65,-1.95) J6(0,-1.95) J7(0.65,-1.95) J8(1.3,-1.95) J9(1.95,-1.95) J10(2.6,-1.95) J11(3.25,-1.95) K1(-3.25,-2.6) K2(-2.6,-2.6) K3(-1.95,-2.6) K4(-1.3,-2.6) K5(-0.65,-2.6) K6(0,-2.6) K7(0.65,-2.6) K8(1.3,-2.6) K9(1.95,-2.6) K10(2.6,-2.6) K11(3.25,-2.6) L1(-3.25,-3.25) L2(-2.6,-3.25) L3(-1.95,-3.25) L4(-1.3,-3.25) L5(-0.65,-3.25) L6(0,-3.25) L7(0.65,-3.25) L8(1.3,-3.25) L9(1.95,-3.25) L10(2.6,-3.25) L11(3.25,-3.25)
CC0402_25
  round 0.635 smd: 1(-0.508,0) 2(0.508,0)
CC0603_OV
  oval 0.889x1.143 smd: 1(-0.762,0) 2(0.762,0)
CC0805_OV
  oval 0.889x1.524 smd: 1(-0.965,0) 2(0.965,0)
CC7343
  rect 2.413x2.591 smd: 1(-3.505,0) 2(3.505,0)
CON24_USB_TYPEC_RA_SMT
  rect 0.305x0.711 smd: A1(-3,3.77) A2(-2.5,3.77) A3(-2,3.77) A4(-1.5,3.77) A5(-1,3.77) A6(-0.5,3.77) A7(0.5,3.77) A8(1,3.77) A9(1.5,3.77) A10(2,3.77) A11(2.5,3.77) A12(3,3.77) B2(2.25,2.47) B3(1.75,2.47) B4(1.25,2.47) B5(0.75,2.47) B6(0.25,2.47) B7(-0.25,2.47) B8(-0.75,2.47) B9(-1.25,2.47) B10(-1.75,2.47) B11(-2.25,2.47)
  rect 0.991x0.711 smd: B1(3.1,2.47) B12(-3.1,2.47)
  oval 1.092x2.108 hole 0.584x1.6: SH1(-4.32,3.36) SH2(4.32,3.36)
  oval 1.092x2.591 hole 0.584x2.083: SH3(4.32,-2) SH4(-4.32,-2)
CON_1X7_SKT_2P54_TH
  rect 1.676x1.676 hole 1.041: 1(0,0)
  round 1.676 hole 1.041: 2(2.54,0) 3(5.08,0) 4(7.62,0) 5(10.16,0) 6(12.7,0) 7(15.24,0)
CON_SKT1X4_TH
  rect 1.651x1.651 hole 1.016: 1(0,0)
  round 1.651 hole 1.016: 2(0,-2.54) 3(0,-5.08) 4(0,-7.62)
CON_SKT1X8_TH
  rect 1.651x1.651 hole 1.016: 1(0,0)
  round 1.651 hole 1.016: 2(0,-2.54) 3(0,-5.08) 4(0,-7.62) 5(0,-10.16) 6(0,-12.7) 7(0,-15.24) 8(0,-17.78)
CON_SKT1X10_TH_104L
  rect 1.651x1.651 hole 1.016: 1(0,0)
  round 1.651 hole 1.016: 2(0,-2.54) 3(0,-5.08) 4(0,-7.62) 5(0,-10.16) 6(0,-12.7) 7(0,-15.24) 8(0,-17.78) 9(0,-20.32) 10(0,-22.86)
CON_SKT2X20_TH
  rect 1.524x1.524 hole 1.041: 1(0,0)
  round 1.524 hole 1.041: 2(-2.54,0) 3(0,-2.54) 4(-2.54,-2.54) 5(0,-5.08) 6(-2.54,-5.08) 7(0,-7.62) 8(-2.54,-7.62) 9(0,-10.16) 10(-2.54,-10.16) 11(0,-12.7) 12(-2.54,-12.7) 13(0,-15.24) 14(-2.54,-15.24) 15(0,-17.78) 16(-2.54,-17.78) 17(0,-20.32) 18(-2.54,-20.32) 19(0,-22.86) 20(-2.54,-22.86) 21(0,-25.4) 22(-2.54,-25.4) 23(0,-27.94) 24(-2.54,-27.94) 25(0,-30.48) 26(-2.54,-30.48) 27(0,-33.02) 28(-2.54,-33.02) 29(0,-35.56) 30(-2.54,-35.56) 31(0,-38.1) 32(-2.54,-38.1) 33(0,-40.64) 34(-2.54,-40.64) 35(0,-43.18) 36(-2.54,-43.18) 37(0,-45.72) 38(-2.54,-45.72) 39(0,-48.26) 40(-2.54,-48.26)
HDR103
  rect 1.524x1.524 hole 1.016: 1(0,0)
  round 1.524 hole 1.016: 2(0,-2.54) 3(0,-5.08)
HDR203
  rect 1.676x1.676 hole 1.016: 1(0,0)
  round 1.676 hole 1.016: 2(2.54,0) 3(0,-2.54) 4(2.54,-2.54) 5(0,-5.08) 6(2.54,-5.08)
HDR205_10M_50_SM_K
  rect 0.737x2.794 smd: 1(-2.54,-2.032) 2(-2.54,2.032) 3(-1.27,-2.032) 4(-1.27,2.032) 5(0,-2.032) 6(0,2.032) 7(1.27,-2.032) 8(1.27,2.032) 9(2.54,-2.032) 10(2.54,2.032)
HDR210
  rect 1.676x1.676 hole 1.016: 1(0,0)
  round 1.676 hole 1.016: 2(2.54,0) 3(0,-2.54) 4(2.54,-2.54) 5(0,-5.08) 6(2.54,-5.08) 7(0,-7.62) 8(2.54,-7.62) 9(0,-10.16) 10(2.54,-10.16) 11(0,-12.7) 12(2.54,-12.7) 13(0,-15.24) 14(2.54,-15.24) 15(0,-17.78) 16(2.54,-17.78) 17(0,-20.32) 18(2.54,-20.32) 19(0,-22.86) 20(2.54,-22.86)
HDR_1X1
  rect 1.676x1.676 hole 1.016: 1(0,0)
HDR_1X2
  rect 1.524x1.524 hole 1.016: 1(0,0)
  round 1.524 hole 1.016: 2(0,-2.54)
HDR_5X2_FTSH_TH_NSP
  rect 0.965x0.965 hole 0.711: 1(0,0)
  round 0.965 hole 0.711: 2(1.27,0) 3(0,-1.27) 4(1.27,-1.27) 5(0,-2.54) 6(1.27,-2.54) 7(0,-3.81) 8(1.27,-3.81) 9(0,-5.08) 10(1.27,-5.08)
IND_0603
  rect 0.991x0.813 smd: 1(-0.69,0) 2(0.69,0)
IND_0805
  rect 1.295x1.499 smd: 1(-0.978,0) 2(0.978,0)
JUMP1X2_0805
  rect 1.295x1.499 smd: 1(-0.965,0) 2(0.965,0)
JUMP2_7P62_TH
  rect 2.134x2.134 hole 1.499: 1(0,0)
  round 2.134 hole 1.499: 2(7.62,0)
LED_0603
  rect 0.838x0.787 smd: A(-0.775,0) C(0.775,0)
MICRO_USB_CONN_9PIN
  rect 1.905x1.905 smd: (-1.2,0) (1.2,0)
  rect 0.406x1.346 smd: 1(-1.3,2.675) 2(-0.65,2.675) 3(0,2.675) 4(0.65,2.675) 5(1.3,2.675)
  rect 2.108x1.6 smd: 6(3.1,2.55) 9(-3.1,2.55)
  rect 1.803x1.905 smd: 7(4,0) 8(-4,0)
MODULE56_1P52_23X23MM
  oval 1.6x0.889 smd: 1(-10.897,8.255) 2(-10.897,6.985) 3(-10.897,5.715) 4(-10.897,4.445) 5(-10.897,3.175) 6(-10.897,1.905) 7(-10.897,0.635) 8(-10.897,-0.635) 9(-10.897,-1.905) 10(-10.897,-3.175) 11(-10.897,-4.445) 12(-10.897,-5.715) 13(-10.897,-6.985) 14(-10.897,-8.255) 29(10.897,-8.255) 30(10.897,-6.985) 31(10.897,-5.715) 32(10.897,-4.445) 33(10.897,-3.175) 34(10.897,-1.905) 35(10.897,-0.635) 36(10.897,0.635) 37(10.897,1.905) 38(10.897,3.175) 39(10.897,4.445) 40(10.897,5.715) 41(10.897,6.985) 42(10.897,8.255)
  oval 0.889x1.6 smd: 15(-8.255,-10.897) 16(-6.985,-10.897) 17(-5.715,-10.897) 18(-4.445,-10.897) 19(-3.175,-10.897) 20(-1.905,-10.897) 21(-0.635,-10.897) 22(0.635,-10.897) 23(1.905,-10.897) 24(3.175,-10.897) 25(4.445,-10.897) 26(5.715,-10.897) 27(6.985,-10.897) 28(8.255,-10.897) 43(8.255,10.897) 44(6.985,10.897) 45(5.715,10.897) 46(4.445,10.897) 47(3.175,10.897) 48(1.905,10.897) 49(0.635,10.897) 50(-0.635,10.897) 51(-1.905,10.897) 52(-3.175,10.897) 53(-4.445,10.897) 54(-5.715,10.897) 55(-6.985,10.897) 56(-8.255,10.897)
  rect 4.445x3.937 smd: 57(-1.122,-0.69)
QFN32_S142EP
  custom 0.07x0.07 smd: 1(-2.4,1.751) 2(-2.4,1.251) 3(-2.4,0.751) 4(-2.4,0.25) 5(-2.4,-0.25) 6(-2.4,-0.751) 7(-2.4,-1.251) 8(-2.4,-1.751) 9(-1.751,-2.4) 10(-1.251,-2.4) 11(-0.751,-2.4) 12(-0.25,-2.4) 13(0.25,-2.4) 14(0.751,-2.4) 15(1.251,-2.4) 16(1.751,-2.4) 17(2.4,-1.751) 18(2.4,-1.251) 19(2.4,-0.751) 20(2.4,-0.25) 21(2.4,0.25) 22(2.4,0.751) 23(2.4,1.251) 24(2.4,1.751) 25(1.751,2.4) 26(1.251,2.4) 27(0.751,2.4) 28(0.25,2.4) 29(-0.25,2.4) 30(-0.751,2.4) 31(-1.251,2.4) 32(-1.751,2.4)
  rect 3.607x3.607 smd: 33(0,0)
RC0402_25
  round 0.635 smd: 1(-0.508,0) 2(0.508,0)
RC0603_OV
  oval 0.889x1.143 smd: 1(-0.762,0) 2(0.762,0)
RC0805_OV
  oval 0.889x1.524 smd: 1(-0.965,0) 2(0.965,0)
REG5_TO263
  rect 1.067x3.2 smd: 1(-3.404,-7.036) 2(-1.702,-7.036) 3(0,-7.036) 4(1.702,-7.036) 5(3.404,-7.036)
  rect 10.795x10.897 smd: 6(0,2.045)
SC70-5
  rect 0.406x0.813 smd: 1(-0.65,-1.079) 2(0,-1.079) 3(0.65,-1.079) 4(0.65,1.079) 5(-0.65,1.079)
SC-88_6P
  rect 0.66x0.305 smd: 1(-0.92,0.65) 2(-0.92,0) 3(-0.92,-0.65) 4(0.92,-0.65) 5(0.92,0) 6(0.92,0.65)
SH0603
  rect 0.991x0.813 smd: 1(-0.8,0) 2(0.8,0)
SH_HDR102_BOTTOM
  rect 1.524x1.524 hole 1.016: 1(0,0)
  round 1.524 hole 1.016: 2(0,-2.54)
SLP1616P6
  rect 0.305x0.635 smd: 1(-0.5,-0.76) 2(0,-0.76) 3(0.5,-0.76) 4(0.5,0.76) 5(0,0.76) 6(-0.5,0.76)
  rect 1.295x0.457 smd: 7(0,0)
SOD-323-A
  rect 0.635x0.838 smd: A(1.115,0) C(-1.115,0)
SOT23_A
  rect 0.787x0.889 smd: 1(-0.94,-1.003) 2(0.94,-1.003) 3(0,1.003)
SOT223
  rect 1.194x2.21 smd: 1(-2.3,-3.1) 2(0,-3.1) 3(2.3,-3.1)
  rect 3.734x2.21 smd: 4(0,3.1)
SW4_SKRP
  rect 1.499x0.762 smd: 1(-2.3,1.075) 2(2.3,1.075) 3(-2.3,-1.075) 4(2.3,-1.075)
TEST_LOOP
  round 1.524 hole 1.016: 1(0,0)
TPAD_030
  round 0.762 smd: 1(0,0)
TPAD_040
  round 1.016 smd: 1(0,0)
UDFN6_1X1P5MM
  rect 0.584x0.305 smd: 1(-0.418,0.5)
  rect 0.508x0.305 smd: 2(-0.38,0) 3(-0.38,-0.5) 4(0.38,-0.5) 5(0.38,0) 6(0.38,0.5)
unnamed#2
  round 1.524 smd: (0,0)
unnamed#3
  round 5.994 hole 3.708: 1(0,0)
WLCSP5_0P4_0P82X1P22
  round 0.254 smd: A1(-0.2,0.4) A2(0.2,0.4) B1(0,0) C1(-0.2,-0.4) C2(0.2,-0.4)
XQFN8_1P45X1P25MM
  rect 0.787x0.203 smd: 1(-0.75,0)
  rect 0.203x0.711 smd: 2(-0.4,-0.65) 3(0,-0.65) 4(0.4,-0.65) 6(0.4,0.65) 7(0,0.65) 8(-0.4,0.65)
  rect 0.711x0.203 smd: 5(0.75,0)
XSON_8P
  rect 0.305x0.61 smd: 1(-0.75,-0.417) 2(-0.25,-0.417) 3(0.25,-0.417) 4(0.75,-0.417) 5(0.75,0.417) 6(0.25,0.417) 7(-0.25,0.417) 8(-0.75,0.417)
XTAL2-3P2X1P5-SM
  rect 1.092x1.905 smd: 1(-1.25,0) 2(1.25,0)
XTAL3_3P35X1P45_SM
  rect 0.406x2.108 smd: 1(1.2,0) 2(0,0) 3(-1.2,0)
XTAL4_3P3X2P6_SM_FL
  rect 1.499x1.194 smd: 1(-1.06,-0.8) 2(1.06,-0.8) 3(1.06,0.8) 4(-1.06,0.8)

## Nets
1V8_VDD: C28.1 C30.1 C37.1 R1.1 R2.3 U7.2 U7.4(TAB)
3V3_5V0: C15.1 C20.1 C32.1 J1.1 J2.1 J4.1 R28.1 TP7.1(PIN1) U5.4
3V3_K82_VOUT: C44.1 C45.1 TP56.1(PIN1) U22.J1
3V3_VDD: C9.1 C29.1 C34.1 J12.4 R2.2 R20.1 R164.1 R165.1 R172.1 R173.1 R177.1 R178.1 R184.1 SH3.2 U6.2(VOUT) U6.4
GND: C1.2 C2.2 C3.2 C4.2 C5.2 C7.2 C9.2 C10.2 C11.2 C14.2 C15.2 C16.2 C17.2 C19.2 C23.2 C24.2 C25.2 C26.2 C28.2 C29.2 C30.2 C31.2 C32.2 C33.2 C34.2 C35.2 C37.2 C38.2 C41.2 C44.2 C45.2 C47.2 C48.2 C49.2 C50.2 C51.2 C52.2 C53.2 C54.2 C55.2 C56.2 C63.2 C64.2 C65.2 C66.2 C67.2 C68.2 C69.2 C78.2 C79.2 C80.2 C81.2 C82.2 C83.2 C84.2 C85.2 C86.2 C87.2 C88.2 C89.2 C91.2 C92.2 C93.1 C94.2 C95.1 C96.2 C98.1 C100.2 C102.2 C104.2 C134.2 C151.2 C152.1 C153.1 C154.2 C155.2 C156.2 C157.2 C158.2 C159.2 C160.2 C161.2 C162.2 D4.A D5.A J6.A1 J6.A12 J6.B1 J6.B12 J7.A1 J7.A12 J7.B1 J7.B12 J8.1 J8.2 J9.1 J9.2 J12.6 J12.7 J13.4 J27.9 J27.10 J28.3 J28.5 J31.4 J32.4 J35.3 J35.5 J43.39 J57.5 J62.3 J62.5 L5.2 L7.2 L9.2 P1.2 P1.5 P1.7 P1.9 P1.12 P1.17 P1.23 P1.38 P1.45 P1.48 P1.50 P1.53 P1.57(EPAD) Q1.2(SOURCE) Q2.2(SOURCE) Q3.2(SOURCE) Q4.2(SOURCE) Q5.2(SOURCE) Q6.2(SOURCE) Q7.2(SOURCE) Q8.2(SOURCE) Q9.2(SOURCE) R3.1 R5.2 R6.2 R7.3 R10.2 R11.2 R13.2 R18.2 R37.2 R64.2 R78.2 R83.2 R85.2 R86.2 R89.1 R201.2 R203.2 R205.2 SJ11.1 SW1.1 SW1.2 SW12.1 SW12.2 TP1.1(PIN1) TP5.1(PIN1) U2.B1(GND) U5.3 U5.6(TAB) U6.1 U17.7 U19.4 U19.5 U20.2 U22.F6 U22.F7 U22.G6 U22.G7 U22.H3 U22.K10 U22.L6 U23.2 U23.3 U25.4 U26.2 U26.8 U26.33 U27.2 U28.2 U29.2 X1.2 Y2.2 Y2.4
P3V3_SDA: C79.1 C80.1 C82.1 C83.1 C84.1 C94.1 C155.1 C157.1 C160.1 C162.1 J61.1 J62.1 R186.1 R187.1 R188.2 R190.2 R197.1 R199.1 R202.1 R206.1 R207.1 U19.1 U20.1 U25.1 U26.1 U26.7 U26.11 U27.5 U28.1 U29.1
P5V0_SDA_USB_CONN_VBUS: J57.1(VBUS) L4.1 U17.6(VBUS)
P5V_SDA: C86.1 L4.2 R198.1 R200.1 U26.6
VBAT: C10.1 C25.1 C35.1 J4.2 P1.49 R26.1
VBATPWR: C3.1 C23.1 P1.46 R17.2
VBUS_DC: D5.C J7.A4 J7.A9 J7.B4 J7.B9(VBUS4) L8.2
VBUS_PA: D4.C J6.A4 J6.A9 J6.B4 J6.B9(VBUS4) L6.2
VDDIO: C16.1 C19.1 P1.44 SH1.2
VDDIO_BRD: J12.2 J28.1 Q1.1 R2.1 R7.2 R56.2 R62.1 R67.2 R68.1 R69.1 R71.2 R90.1 R91.1 SH1.1 SH5.1 SH6.1 SH7.2 TP6.1(PIN1)
VDDPA: P1.52 R26.2
ANT_1: J29.2 J29.3 J30.2 J30.3 R73.2 R74.2 R79.2 R80.2
C_TX1: C95.2 C97.2 C98.2 C105.2 R74.1 R75.2 R79.1
C_TX2: C96.1 C100.1 C101.2 C103.2 R73.1 R80.1 R81.2
DC5V: C134.1 J5.3 J43.2 J43.4 SJ10.1
EXT_MODE_SWITCH_SP: J27.6 R144.2
EXT_MODE_SWITCH_SP_DONE: J27.8 R122.1
EXTAL32: U22.L5 Y1.1
GREEN_LED: J43.19 R15.2 SJ8.1
J_VBATPWR: C7.1 C26.1 J2.2 R17.1
J_VUP: C5.1 C11.1 J1.2 R23.1
JTAG_TDO: J28.6 R56.1
JTAG_TMS_SWDIO: J28.2 P1.25 R67.1
K82_JTAG_RST: J35.10(B5) SH2.2
K82_MODE_SWITCH_SP: J27.5 U22.B9
K82_MODE_SWITCH_SP_DONE: J27.7 U22.D8
K82_NFC_IRQ: J27.19 U22.F8
K82_PTA20: J27.1 U22.H5
K82_PTA21: J27.3 U22.J5
K82_SPI1_CLK: J27.13 U22.C10
K82_SPI1_CS0: J27.15 U22.D10
K82_SPI1_MISO: J27.11 U22.E9
K82_SPI1_MOSI: J27.17 U22.B10
LEDGR: D3.A R178.2
LEDRR: D2.A R177.2
LP3856_ADJ_R: C20.2 J3.1 R5.1 R28.2 U5.5
LVLRST_EN: R188.1 U25.5
MCU_VBAT: C52.1 SH6.2 U22.K6
MCU_VDD: C41.1 C53.1 C54.1 C55.1 C56.1 C151.1 J35.1 R36.1 R38.1 R180.1 R183.1 SH4.1 SH5.2 U22.E6 U22.E7 U22.L10 U23.5
MCU_VDDA: C50.1 C51.1 SH4.2 U22.F5 U22.G5
NFC_AUX1: J10.3 P1.18
NFC_AUX2: J10.2 P1.19
NFC_CLK: P1.22 TP33.1(PIN1)
NFC_CLK_AUX: J15.5 P1.56 TP50.1(PIN1)
NFC_DWL_REQ: J14.1 P1.27
NFC_GPIO0: J13.9 P1.28 TP19.1(PIN1)
NFC_GPIO1: J13.10 P1.31 TP18.1(PIN1)
NFC_GPIO3: P1.30 R8.1
NFC_GPIO4: J14.2 P1.32 TP16.1(PIN1)
NFC_GPIO5: J13.2 P1.33 TP17.1(PIN1)
NFC_GPIO6: J13.6 P1.16 TP25.1(PIN1)
NFC_GPIO7: J13.7 P1.13 TP26.1(PIN1)
NFC_GPIO8: J13.5 P1.14 TP27.1(PIN1)
NFC_GPIO9: J13.8 P1.15 TP28.1(PIN1)
NFC_HOST_SEL0: P1.20 R7.1
NFC_HOST_SEL1: P1.21 R89.2
NFC_I2C_IRQ: P1.3 R152.2 TP15.1(PIN1)
NFC_I2C_SCL: P1.40 R90.2 R127.2
NFC_I2C_SDA: P1.39 R8.2 R91.2 R137.2
NFC_INT_AUX: J15.4 P1.54 TP43.1(PIN1)
NFC_IO_AUX: J15.3 P1.55 TP39.1(PIN1)
NFC_IRQ: J27.20 P1.26 SJ4.1
NFC_JTAG_RST: D12.1 D12.2 R60.2 TP24.1(PIN1)
NFC_MODE_SWITCH: P1.29 R16.2 R141.1 SJ3.1
NFC_RXN: J31.6 J32.6 P1.4 R75.1 R76.2
NFC_RXP: J31.2 J32.2 P1.10 R77.1 R81.1
NFC_SPI_CLK: J27.14 P1.35
NFC_SPI_MISO: J27.12 P1.34
NFC_SPI_MOSI: J27.18 P1.37
NFC_SPI_NSS: J27.16 P1.36
NFC_TX1: C93.2 C97.1 C102.1 C105.1 J31.5 J32.5 P1.6 R76.1
NFC_TX2: C92.1 C101.1 C103.1 C104.1 J31.3 J32.3 P1.8 R77.2
NFC_VEN: P1.43 R15.3 R142.1 SJ9.1
NMI_B: R180.2 U22.J8
NRESET: D12.3(C) J28.10(B5)
PTA0: J35.4 J60.1 R37.1 U22.L7
PTA1: R47.2 U22.H8
PTA2: R39.2 U22.J7
PTA3: J35.2 J59.1 R36.2 U22.H9
PTA18: C152.2 R181.2 U22.L11 Y2.3
PTA19: C153.2 R181.1 U22.K11 Y2.1
PTC7: SJ12.1 U22.B7
PTC8: SJ13.1 U22.A7
PU-R_RST_B: C91.1 R60.1 R68.2
PWR_ON: D1.A R20.2
R_5V0_ADJ: J3.2 R6.1
RST_TGTMCU_B: D8.C(CATHODE) J56.3 R183.2 R185.2 R195.2 SH2.1 U22.J11 U23.4(Y) U25.7
SDA_EXTAL: C88.1 U26.17 X1.3
SDA_JTAG_TCLK: J62.4 U26.12
SDA_JTAG_TDI: J62.8 U26.13
SDA_JTAG_TDO: J62.6 U26.14
SDA_JTAG_TMS: J62.2 R207.2 U26.15
SDA_LED: D9.C(CATHODE) TP74.1(PIN1) U26.29
SDA_LED_R: D9.A R199.2
SDA_RST: J62.10(B5) R83.1 R198.2 TP72.1(PIN1) U26.19
SDA_RST_LED: D8.A R191.2
SDA_RST_TGTMCU_B: J58.2 U26.21
SDA_RST_TGTMCU_J_B: J56.1 J58.1 R186.2 R195.1 U25.2
SDA_RX_EN: R78.1 R197.2 U28.5
SDA_SPI0_CS: R209.2 TP70.1(PIN1) U26.23
SDA_SPI0_RST_B: R208.2 TP69.1(PIN1) U26.22
SDA_SPI0_SCK: TP77.1(PIN1) U26.26 U29.3
SDA_SPI0_SIN: TP73.1(PIN1) U19.3 U26.28
SDA_SPI0_SOUT: TP75.1(PIN1) U20.3 U26.27
SDA_SWD_EN: R204.1 R208.1 U27.6
SDA_SWD_EN_B: R189.2 U26.16
SDA_SWD_EN_B_R: R187.2 R189.1 U27.1
SDA_SWD_EN_R: R204.2 R205.1 R206.2 U29.5
SDA_SWD_OE: R84.1 R209.1 U27.4(Y2)
SDA_SWD_OE_B: R192.2 U26.20
SDA_SWD_OE_B_R: R190.1 R192.1 U27.3
SDA_SWD_OE_R: R84.2 R201.1 R202.2 U20.5
SDA_USB_CONN_DN: J57.2 R193.1 U17.1
SDA_USB_CONN_DP: J57.3 R194.1 U17.2
SDA_USB_DN: R193.2 U26.4
SDA_USB_DP: R194.2 U26.3
SDA_USB_P5V_SENSE: R200.2 R203.1 TP76.1(PIN1) U26.30
SDA_USBSHIELD: J57.6 J57.7 J57.8 J57.9 L5.1
SDA_VOUT33: C89.1 J61.2 U26.5
SDA_XTAL: C87.1 U26.18 X1.1
SDB: R21.2 U5.1
SH_3V3_VDDIO_E: C49.1 C78.1 SH3.1 U22.E5
SPARE_GPIO1: TP58.1(PIN1) U22.F4
SPARE_GPIO2: TP59.1(PIN1) U22.G3
SPARE_GPIO3: TP60.1(PIN1) U22.G4
SPARE_GPIO4: TP61.1(PIN1) U22.H4
SW1_RST_B: C85.1 J56.2 SW12.3 SW12.4
SWD_CLK_TGTMCU_BUF: J60.2 U29.4
SWD_DIO_TGTMCU_BUF: J59.2 U19.6 U20.4
TC_EXTAL_TP: TP66.1(PIN1) U26.10
TC_SDA_USB_ID_TP: J57.4 TP65.1(PIN1) U17.3
TC_XTAL_TP: TP67.1(PIN1) U26.9(XTAL32)
TDI: J35.8 R38.2 R47.1
TDO: J35.6 R39.1
TP_2102_A: TP63.1(PIN1) U25.3
TP_2102_B: TP64.1(PIN1) U25.6
UART1_RX_TGTMCU: R196.2 U22.A5
UART1_RX_TGTMCU_BUF: R196.1 U28.4
UART1_RX_TGTMCU_R: TP68.1(PIN1) U26.25 U28.3
UART1_TX_TGTMCU: R82.2 U22.B5
UART1_TX_TGTMCU_BUF: R82.1 U19.7
UART1_TX_TGTMCU_R: TP71.1(PIN1) U19.2 U26.24
USB0_DM: R9.2 U22.H1
USB0_DP: R182.2 U22.H2
USB0_RDN: R9.1 R25.1
USB0_RDP: R27.1 R182.1
USB_5V_DC: C47.1 C66.1 C67.1 C68.1 C69.1 J5.5 L8.1 TP3.1(PIN1) U22.J2
USB_5V_PA: C24.1 C63.1 C64.1 C65.1 J5.1 L6.1 TP2.1(PIN1)
USB_CC1_DC: J7.A5 R11.1 TP10.1(PIN1)
USB_CC1_PA: J6.A5 R86.1 TP8.1(PIN1)
USB_CC2_DC: J7.B5 R10.1 TP11.1(PIN1)
USB_CC2_PA: J6.B5 R85.1 TP9.1(PIN1)
USB_DC_SHLD: J7.SH1 J7.SH2 J7.SH3 J7.SH4 L9.1
USB_DN: J7.A7 J7.B7 U2.A2
USB_DP: J7.A6 J7.B6 U2.A1
USB_PA_SHLD: J6.SH1 J6.SH2 J6.SH3 J6.SH4 L7.1
V_TGTMCU: C81.1 C156.1 C158.1 C159.1 C161.1 R185.1 R191.1 SH7.1 U19.8(VCCB) U20.6(VCCB) U25.8(VCCB) U28.6(VCCB) U29.6(VCCB)
VMAIN: C1.1 C2.1 C14.1 C17.1 C33.1 C38.1 J5.2 J5.4 J5.6(B3) J12.5 R21.1 U5.2 U6.3 U7.3
VREF_OUT: C48.1 TP57.1(PIN1) U22.L3
VUP: C4.1 C31.1 J33.1 P1.51 R23.2
XTAL32: U22.L4(XTAL32) Y1.2
YELLOW_LED: J43.23 R16.3 SJ7.1
N27599440: J29.1 J30.1
N27599525: J29.4 J30.4
N27867846: P1.11 TP52.1(PIN1)
N27989341: D1.C(CATHODE) Q1.3
N27993186: P1.41 TP20.1(PIN1)
N27993212: P1.42 TP32.1(PIN1)
N28179141: J28.8 R71.1
N28179177: J28.4 P1.24 R64.1
N28179212: J28.9 SJ11.2
N28179372: D11.A R62.2
N28179376: D15.A R69.2
N28179481: D11.C(CATHODE) Q6.3
N28179485: D15.C(CATHODE) Q7.3
N28319858: R1.2 R4.1 R14.1 U7.1
N28319891: R3.2 R4.2
N28319921: R3.3 R14.2
N28331755: D16.A R164.2
N28331792: D16.C(CATHODE) Q4.3
N28331794: D17.A R165.2
N28331876: Q4.1 SJ7.2
N28331878: D18.A R172.2
N28331886: D17.C(CATHODE) Q5.3
N28332010: D18.C(CATHODE) Q2.3
N28332022: Q5.1 SJ8.2
N28332036: D19.A R173.2
N28332155: J43.5 R127.1
N28332189: J43.3 R137.1
N28332225: J43.40 R142.2
N28332293: D19.C(CATHODE) Q3.3
N28332350: J43.38 R141.2
N28421669: Q2.1 SJ9.2
N28421722: Q3.1 SJ10.2
N28430174: J10.1 R8.3
N28430681: Q6.1 SJ3.2
N28430684: Q7.1 SJ4.2
N28495927: D3.C(CATHODE) Q9.3
N28496386: C154.1 R184.2 SW1.3 SW1.4 TP62.1(PIN1) U23.1
N28503659: J27.4 R16.1
N28503664: J27.2 R15.1
N28509733: J43.24 R122.2
N28509890: J43.21 R144.1
N28538592: Q8.1 SJ12.2
N28538615: Q9.1 SJ13.2
N28539455: D2.C(CATHODE) Q8.3
N28651788: J43.37 R152.1
N28673617: R12.1 U2.C1
N28673619: R12.2 R13.1 R27.2
N28673663: R19.1 U2.C2
N28673665: R18.1 R19.2 R25.2

Pads without a net: J6 A2 A3 A6 A7 A8 A10 A11 B2 B3 B6 B7 B8 B10 B11; J7 A2 A3 A8 A10 A11 B2 B3 B8 B10 B11; J12 1 3 8; J13 1 3; J14 3 4 5 6 7 8; J15 1 2 6 7 8; J28 7; J31 1 7; J32 1 7; J35 7 9; J43 1 6 7 8 9 10 11 12 13 14 15 16 17 18 20 22 25 26 27 28 29 30 31 32 33 34 35 36; J62 7 9; NOREF#58 1; NOREF#75 1; P1 1 47; U17 4 5; U22 A1 A2 A3 A4 A6 A8 A9 A10 A11 B1 B2 B3 B4 B6 B8 B11 C1 C2 C3 C4 C5 C6 C7 C8 C9 C11 D1 D2 D3 D4 D5 D6 D7 D9 D11 E1 E2 E3 E4 E8 E10 E11 F1 F2 F3 F9 F10 F11 G1 G2 G8 G9 G10 G11 H6 H7 H10 H11 J3 J4 J6 J9 J10 K1 K2 K3 K4 K5 K7 K8 K9 L1 L2 L8 L9; U26 31 32

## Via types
v1: diameter 0.457, hole 0.203, TOP to BOTTOM, 120 vias
v2: diameter 0.508, hole 0.254, TOP to BOTTOM, 336 vias
v3: diameter 0.508, hole 0.257, TOP to BOTTOM, 137 vias
v4: diameter 0.305, hole 0.152, TOP to BOTTOM, 4 vias

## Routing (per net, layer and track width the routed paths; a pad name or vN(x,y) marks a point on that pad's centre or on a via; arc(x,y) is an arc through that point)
1V8_VDD:
  vias: v2(169.61,22.98) v2(169.62,21.82) v2(170.88,22.98) v2(170.89,21.82) v2(172.15,22.98) v2(172.16,21.82)
3V3_K82_VOUT: length 10.3
  TOP w0.254: U22.J1 123.24,35.3 123.49,35.55 v2(123.49,35.57)
  TOP w0.457: TP56.1 127.38,40.82 v2(127.08,40.51)
  BOTTOM w0.457: C44.1 125.97,38.79 127.08,39.89 v2(127.08,40.51)
  BOTTOM w0.508: C44.1 125.04,36.33 124.29,35.58 124.14,35.58 124.13,35.57 v2(123.49,35.57) 123.49,35.6 123.19,35.9 C45.1
3V3_VDD: length 55.7
  TOP w0.508: v2(129.62,18.16) 135.84,24.38 135.84,34.92 138.02,37.11 138.02,45.22 136.36,46.88 127.44,46.88 126.8,47.52 R184.1
  BOTTOM w0.508: R177.1 v2(175.41,22.71) ; R172.1 175.61,20.17 v2(175.34,20.45) ; R20.1 176.52,25.23 175.45,25.23 v2(175.41,25.27) ; R165.1 175.34,18.54 v2(175.34,17.53) 176.45,17.53 R164.1 ; R178.1 175.43,23.9 175.36,23.98 v2(175.24,23.98) ; SH3.2 117.44,25.55 v2(116.45,26.54) ; R173.1 v2(175.35,21.46)
  vias: v2(168.48,15.04) v2(168.48,14.12) v2(169.11,12.8) v2(170.03,12.8)
GND: length 134.1
  TOP w0.203: U27.2 v2(146.15,37.64)
  TOP w0.254: U22.F6 v1(119.18,33.68) ; v1(118.53,33.67) U22.G7 ; v2(157.64,46.33) 157.77,46.2 157.77,45.77 158.15,45.39 158.34,45.39 R18.2 ; U22.G6 v1(119.83,34.33) ; U22.K10 v1(116.58,35.63) ; U22.F7 118.86,33.35 v1(119.18,33.03) ; v2(171.44,16.64) 171.3,16.5 R3.1 ; U22.H3 v1(121.13,34.98) ; U25.4 155.69,46.55 155.75,46.61 v2(155.75,47.05) ; U22.L6 v1(119.83,36.28)
  TOP w0.305: v2(178.43,51.31) 178.49,51.36 J6.A1 178.49,53.66 J6.B12 ; v2(156.29,51.56) 156.49,51.77 J7.A12 156.49,53.66 J7.B1 ; J6.B1 172.49,53.66 J6.A12 v2(172.49,51.49) ; C155.2 163.63,38.58 v2(163.51,38.46) ; D4.A 179.37,50.28 v2(179.68,50.6) ; J7.B12 162.49,53.66 J7.A1 162.49,51.66 v2(162.72,51.43)
  TOP w0.381: J57.5 181.03,42.75 v2(180.52,43.26) ; U17.7 177.73,42.41 v2(177.57,42.57)
  TOP w0.457: C151.2 v2(116.92,40.5) ; v2(170.53,45.69) 170.52,45.68 C82.2
  TOP w0.505: v2(85.23,29.14) P1.7 ; C100.2 v2(65.63,30.07) C95.1 ; C96.2 v2(63.73,30.05) C98.1 ; P1.5 v2(85.23,31.68)
  TOP w0.508: D4.A 178.43,50.66 v2(178.43,51.31) ; C93.1 72.98,30.61 J32.4 72.96,29.39 C92.2 ; P1.53 v2(92.91,38.09) ; 96.72,39.4 v2(96.72,41.45) ; v3(164.03,50.02) 163.17,50.88 163.17,50.99 v2(162.72,51.43) ; C162.2 159.82,43.44 v2(160.19,43.44) ; C153.1 111.71,32.59 Y2.4 110.94,34.5 v2(110.59,34.85) 110.59,38.86 v2(110.92,39.19) 112.6,39.19 113.23,38.56 C152.1 113.23,36.7 Y2.2 114.17,36.62 v2(114.38,36.83) ; J28.3 122.17,19.21 v2(121.51,19.86) 120.9,19.25 J28.5 ; R6.2 v2(138.58,14.45) ; C94.2 164.51,45.38 v2(164.68,45.22) ; D5.A 155,51.19 v2(154.76,51.43) ; C79.2 154.25,42.33 J62.3 ; 91.64,17.6 v2(91.64,19.3) ; P1.23 v2(99.26,19.3) ; SW1.1 v2(130.15,50.88) ; v2(103.27,41.45) 103.07,41.25 P1.45 ; SW1.2 v2(137.55,50.88) ; v2(162.89,41.61) 162.46,41.18 C160.2 ; SW12.1 v2(130.62,44.76) ; v2(176.5,38.8) 177.52,38.8 C86.2 ; SW12.2 v2(135.22,44.76) ; P1.2 v2(84.73,35.49) ; R64.2 v2(122.17,9.3) ; P1.12 v2(87.78,22.79) ; P1.38 v2(106.71,31.68) ; C154.2 v2(127.69,48.25) ; v2(98.67,40.71) 99.26,40.12 P1.48 ; R37.2 122.74,50.04 v2(122.91,49.87) ; R89.1 v2(97.71,13.82)
  BOTTOM w0.203: v2(160.33,50.1) 159.84,50.1 159.84,50.09 U2.B1 ; v2(170.53,45.69) 170.42,45.58 U26.8
  BOTTOM w0.254: U19.5 v2(162.91,36.49) ; v2(164.68,45.22) 164.15,44.69 U20.2 ; C10.2 99.33,37.25 C25.2 99.33,36.34 99.74,35.94 99.76,35.94 99.97,35.73 C35.2
  BOTTOM w0.305: U19.4 163.14,38.09 v2(163.51,38.46) 164.03,37.95 U28.2 ; C47.2 120.8,35.34 121.13,35.01 v1(121.13,34.98) ; C54.2 119.58,33.03 v1(119.18,33.03) ; C55.2 118.18,33.38 118.48,33.67 v1(118.53,33.67) ; U29.2 v2(162.89,41.61) ; C78.2 118.86,30.1 v1(118.53,30.43) 117.83,31.13 C56.2 ; v3(165.22,35.39) 165.75,35.91 165.75,36 R78.2 ; v2(114.52,37.71) 114.9,37.33 114.9,37.27 C53.2 ; U26.2 166.85,46.4 v3(167,46.55) ; C52.2 119.53,37.39 119.83,37.08 v1(119.83,36.28) ; v2(118.06,22.1) 117.81,22.35 Q9.2
  BOTTOM w0.381: 169.61,36.84 170.26,36.18 C88.2 ; 169.61,36.84 169.09,36.32 C87.2 ; 169.61,36.84 X1.2 ; v2(112.2,29.36) 111.38,29.36 U23.2 ; R203.2 164.02,47.13 163.78,47.37 163.78,47.42 v2(163.75,47.45) ; U23.3 v2(110.53,29.99)
  BOTTOM w0.508: C88.2 170.26,35.49 v2(169.75,34.98) ; C49.2 119.33,30.86 C78.2 ; v2(131.52,35.56) 130.89,35.56 130.78,35.66 C134.2 ; Q7.2 v2(108.13,4.11) ; v2(148.9,41.14) 148.99,41.14 149.36,41.51 R83.2 ; C48.2 122.26,39.07 v2(123.19,38.13) ; C44.2 124.68,40.31 124.09,39.72 124.09,39.03 v2(123.19,38.13) ; C45.2 v2(123.19,38.13) ; C80.2 147.36,37.77 147.28,37.69 146.2,37.69 v2(146.15,37.64) ; C81.2 155.52,46.04 155.75,46.27 v2(155.75,47.05) ; R205.2 157.67,42.07 v2(157.6,42.14) ; Q6.2 v2(103.4,4.09)
  vias: v2(78.69,19.05) v2(78.69,16.51) v2(78.69,13.97) v2(78.69,12.07) v2(78.69,10.16) v2(80,28.75) v2(80.28,26.95) v2(80.38,32.36) v2(80.41,29.82) v2(80.54,24.36) v2(80.61,34.9) v2(80.77,36.02) v2(80.82,26.21) v2(80.87,21.92) v2(80.89,28.78) v2(81.17,23.24) v2(81.25,32.59) v2(81.38,29.59) v2(81.5,34.47) v2(81.53,27) v2(81.53,24.38) v2(81.58,31.74) v2(81.73,35.48) v2(81.83,28.75) v2(82.04,26.21) v2(82.24,22.33) v2(82.32,32.23) v2(82.47,36.22) v2(82.47,29.51) v2(82.52,23.44) v2(82.59,34.09) v2(82.72,27) v2(82.75,24.36) v2(82.95,35.03) v2(82.9,31.56) v2(83,28.78) v2(83.25,26.21) v2(83.33,22.4) v2(83.52,32.19) v2(83.59,29.51) v2(83.64,23.34) v2(83.69,52.65) v2(83.87,36.09) v2(83.84,33.96) v2(83.79,24.38) v2(83.89,27) v2(84.26,31.7) v2(84.28,57.33) v2(84.52,26.24) v2(84.76,24.41) v2(84.94,33.91) v2(85.03,27.03) v2(86.54,56.59) v2(89.56,4.06) v2(91.75,51.38) v2(92.82,52.55) v2(93.5,9.68) v2(94.3,52.57) v2(94.39,13.82) v2(95.52,52.32) v2(97.61,41.63) v2(97.61,40.69) v2(98.67,41.65) v2(100.22,37.38) v2(100.86,36.37) v2(100.86,35.1) v2(101.22,13.64) v2(102.11,12.27) v2(102.95,56.54) v2(104.23,51.41) v2(104.23,50.26) v2(104.41,41.7) v2(104.41,40.81) v2(105.36,23.93) v2(105.38,51.41) v2(105.38,50.26) v2(105.43,41.7) v2(105.43,40.81) v2(105.69,19.25) v2(106.12,24.82) v2(106.76,16.74) v2(106.81,23.98) v2(107.26,18.36) v2(108.23,44.32) v2(108.51,54.74) v2(108.86,44.96) v2(109.14,18.69) v2(109.73,15.75) v2(119.96,40.64) v2(122,24.38) v2(125.53,16.59) v2(127.08,22.73) v2(127.46,17.78) v2(128.22,37.23) v2(128.19,35.83) v2(132.95,45.75) v2(140.41,52.46) v2(141.45,17.27) v2(142.77,15.36) v2(146.13,23.24) v2(159.41,5.51) v2(162.38,18.16) v2(164.03,26.8) v2(164.79,20.7) v2(166.28,58.79) v2(166.29,57.63) v2(166.95,1.9) v2(167.55,58.79) v2(167.56,57.63) v2(174.57,1.9) v2(179.06,40.23) v2(179.27,1.6) v2(179.32,3.84) v2(180.07,33.65) v2(180.08,5.66) v2(180.96,33.09) v3(94.97,29.08) v3(94.97,27.81) v3(94.97,26.54) v3(96.24,29.08) v3(96.24,27.81) v3(96.24,26.54) v3(97.51,29.08) v3(97.51,27.81) v3(97.51,26.54) v3(141.23,13.94) v3(141.23,12.67) v3(141.23,11.4) v3(141.23,10.13) v3(141.23,8.86) v3(141.23,7.59) v3(141.23,6.32) v3(141.23,5.05) v3(141.23,3.78) v3(142.5,13.94) v3(142.5,12.67) v3(142.5,11.4) v3(142.5,10.13) v3(142.5,8.86) v3(142.5,7.59) v3(142.5,6.32) v3(142.5,5.05) v3(142.5,3.78) v3(143.77,13.94) v3(143.77,12.67) v3(143.77,11.4) v3(143.77,10.13) v3(143.77,8.86) v3(143.77,7.59) v3(143.77,6.32) v3(143.77,5.05) v3(143.77,3.78) v3(145.04,13.94) v3(145.04,12.67) v3(145.04,11.4) v3(145.04,10.13) v3(145.04,8.86) v3(145.04,7.59) v3(145.04,6.32) v3(145.04,5.05) v3(145.04,3.78) v3(146.31,13.94) v3(146.31,12.67) v3(146.31,11.4) v3(146.31,10.13) v3(146.31,8.86) v3(146.31,7.59) v3(146.31,6.32) v3(146.31,5.05) v3(146.31,3.78) v3(147.58,13.94) v3(147.58,12.67) v3(147.58,11.4) v3(147.58,10.13) v3(147.58,8.86) v3(147.58,7.59) v3(147.58,6.32) v3(147.58,5.05) v3(147.58,3.78) v3(148.85,13.94) v3(148.85,12.67) v3(148.85,11.4) v3(148.85,10.13) v3(148.85,8.86) v3(148.85,7.59) v3(148.85,6.32) v3(148.85,5.05) v3(148.85,3.78) v3(150.12,13.94) v3(150.12,12.67) v3(150.12,11.4) v3(150.12,10.13) v3(150.12,8.86) v3(150.12,7.59) v3(150.12,6.32) v3(150.12,5.05) v3(150.12,3.78) v3(150.67,50.59) v3(151.39,13.94) v3(151.39,12.67) v3(151.39,11.4) v3(151.39,10.13) v3(151.39,8.86) v3(151.39,7.59) v3(151.39,6.32) v3(151.39,5.05) v3(151.39,3.78) v3(151.57,50.59) v3(152.46,50.59) v3(153.59,50.95) v3(160.46,39.22) v3(160.46,36.22) v3(162.26,43.13) v3(162.86,47.35) v3(164.03,48.61) v3(166.84,41.89) v3(166.89,44.25) v3(166.89,43.21) v3(168.1,44.45) v3(168.12,43.21) v3(168.47,41.87) v3(169.36,43.3) v3(169.37,44.45) v3(169.37,41.91) v3(177.72,45.82) v3(179.01,46.73) v3(179.99,46.73) v3(180.91,46.73) v3(184.4,53.01) v3(184.48,51.59)
